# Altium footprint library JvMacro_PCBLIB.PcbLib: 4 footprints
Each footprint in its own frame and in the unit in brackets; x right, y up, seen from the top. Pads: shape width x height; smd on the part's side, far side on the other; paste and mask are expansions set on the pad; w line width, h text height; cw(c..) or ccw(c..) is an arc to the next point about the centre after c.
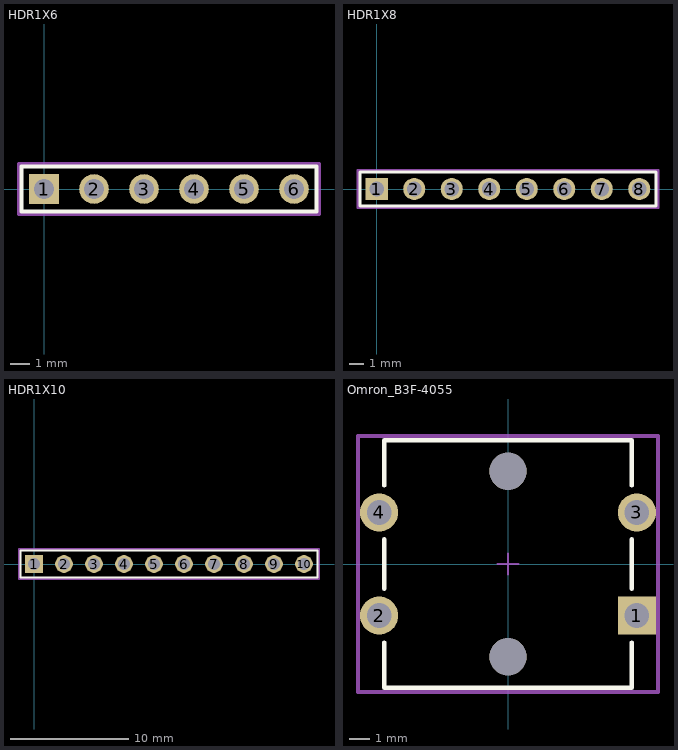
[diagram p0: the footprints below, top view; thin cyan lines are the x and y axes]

## HDR1X6 [mm] "Connector; Header; 6 Position; Vertical"
pads (6):
  rect 1.5x1.5 hole 1: 1(0,0)
  round 1.5 hole 1: 2(2.54,0) 3(5.08,0) 4(7.62,0) 5(10.16,0) 6(12.7,0)
Top Overlay:
  lines w0.2: -1.143,-1.143 13.843,-1.143 13.843,1.143 -1.143,1.143 -1.143,-1.143
Mechanical 15:
  lines w0.2: -1.27,-1.27 13.97,-1.27 13.97,1.27 -1.27,1.27 -1.27,-1.27
3D body "User Library-Header Single Pin.STEP": height 6.54, standoff -2.46, extent -1.27,-1.27 1.27,1.27
3D body "User Library-Header Single Pin.STEP": height 6.54, standoff -2.46, extent 1.27,-1.27 3.81,1.27
3D body "User Library-Header Single Pin.STEP": height 6.54, standoff -2.46, extent 3.81,-1.27 6.35,1.27
3D body "User Library-Header Single Pin.STEP": height 6.54, standoff -2.46, extent 6.35,-1.27 8.89,1.27
3D body "User Library-Header Single Pin.STEP": height 6.54, standoff -2.46, extent 8.89,-1.27 11.43,1.27
3D body "User Library-Header Single Pin.STEP": height 6.54, standoff -2.46, extent 11.43,-1.27 13.97,1.27

## HDR1X8 [mm] "Connector; Header; 8 Position; Vertical"
pads (8):
  rect 1.5x1.5 hole 1: 1(0,0)
  round 1.5 hole 1: 2(2.54,0) 3(5.08,0) 4(7.62,0) 5(10.16,0) 6(12.7,0) 7(15.24,0) 8(17.78,0)
Top Overlay:
  lines w0.2: -1.143,-1.143 -1.143,1.143 18.923,1.143 18.923,-1.143 -1.143,-1.143
Mechanical 15:
  lines w0.2: -1.27,-1.27 -1.27,1.27 19.05,1.27 19.05,-1.27 -1.27,-1.27
3D body "User Library-Header Single Pin.STEP": height 6.54, standoff -2.46, extent 16.51,-1.27 19.05,1.27
3D body "User Library-Header Single Pin.STEP": height 6.54, standoff -2.46, extent 13.97,-1.27 16.51,1.27
3D body "User Library-Header Single Pin.STEP": height 6.54, standoff -2.46, extent 11.43,-1.27 13.97,1.27
3D body "User Library-Header Single Pin.STEP": height 6.54, standoff -2.46, extent 8.89,-1.27 11.43,1.27
3D body "User Library-Header Single Pin.STEP": height 6.54, standoff -2.46, extent 6.35,-1.27 8.89,1.27
3D body "User Library-Header Single Pin.STEP": height 6.54, standoff -2.46, extent 3.81,-1.27 6.35,1.27
3D body "User Library-Header Single Pin.STEP": height 6.54, standoff -2.46, extent 1.27,-1.27 3.81,1.27
3D body "User Library-Header Single Pin.STEP": height 6.54, standoff -2.46, extent -1.27,-1.27 1.27,1.27

## HDR1X10 [mm] "Connector; Header; 10 Position; Vertical"
pads (10):
  rect 1.5x1.5 hole 1: 1(0,0)
  round 1.5 hole 1: 2(2.54,0) 3(5.08,0) 4(7.62,0) 5(10.16,0) 6(12.7,0) 7(15.24,0) 8(17.78,0) 9(20.32,0) 10(22.86,0)
Top Overlay:
  lines w0.2: -1.143,-1.143 24.003,-1.143 24.003,1.143 -1.143,1.143 -1.143,-1.143
Mechanical 15:
  lines w0.2: -1.27,-1.27 24.13,-1.27 24.13,1.27 -1.27,1.27 -1.27,-1.27
3D body "User Library-Header Single Pin.STEP": height 6.54, standoff -2.46, extent -1.27,-1.27 1.27,1.27
3D body "User Library-Header Single Pin.STEP": height 6.54, standoff -2.46, extent 1.27,-1.27 3.81,1.27
3D body "User Library-Header Single Pin.STEP": height 6.54, standoff -2.46, extent 3.81,-1.27 6.35,1.27
3D body "User Library-Header Single Pin.STEP": height 6.54, standoff -2.46, extent 6.35,-1.27 8.89,1.27
3D body "User Library-Header Single Pin.STEP": height 6.54, standoff -2.46, extent 8.89,-1.27 11.43,1.27
3D body "User Library-Header Single Pin.STEP": height 6.54, standoff -2.46, extent 11.43,-1.27 13.97,1.27
3D body "User Library-Header Single Pin.STEP": height 6.54, standoff -2.46, extent 13.97,-1.27 16.51,1.27
3D body "User Library-Header Single Pin.STEP": height 6.54, standoff -2.46, extent 16.51,-1.27 19.05,1.27
3D body "User Library-Header Single Pin.STEP": height 6.54, standoff -2.46, extent 19.05,-1.27 21.59,1.27
3D body "User Library-Header Single Pin.STEP": height 6.54, standoff -2.46, extent 21.59,-1.27 24.13,1.27

## Omron_B3F-4055 [mm]
pads (6):
  rect 1.85x1.85 hole 1.2 paste-1000 mask+0: 1(6.25,-2.5)
  round 1.85 hole 1.2 paste-1000 mask+0: 2(-6.25,-2.5) 3(6.25,2.5) 4(-6.25,2.5)
  round 1.8 hole 1.8 unplated paste-1000 mask+0: ""(0,-4.5) ""(0,4.5)
Top Overlay:
  lines w0.2: -6,-3.8 -6,-6 6,-6 6,-3.8 ; -6,-1.2 -6,1.2 ; -6,3.8 -6,6 6,6 6,3.8 ; 6,-1.2 6,1.2
Mechanical 15:
  lines w0.1: -0.5,0 0.5,0 ; 0,-0.5 0,0.5
  lines w0.2: -7.275,-6.2 7.275,-6.2 ; -7.275,-6.2 -7.275,6.2 ; -7.275,-6.2 7.275,-6.2 ; -7.275,-6.2 -7.275,6.2 ; -7.275,6.2 7.275,6.2 ; -7.275,6.2 7.275,6.2 ; 7.275,-6.2 7.275,6.2 ; 7.275,-6.2 7.275,6.2
3D body "Switch_Omron_B3F-4055_eec.STEP": height 10.03, standoff -3.47, extent -6.9,-6 6.9,6
3D body: height 10.5, standoff 5, extent -5.588,-5.588 5.588,5.588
